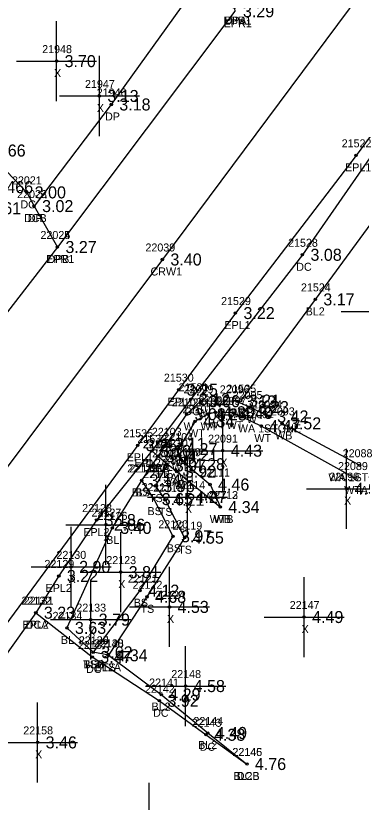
# Model space of a CAD drawing. Extents: x 2608745 to 2610333, y 641917 to 643463.
# Drawn here: x 2610015.6 to 2610058.8, y 641978.2 to 642076.5 of the extents above; entities that cross this region are included whole.
import ezdxf

# ---------------------------------------------------------------- set-up
doc = ezdxf.new("R2010")
doc.units = 0
for name, color, linetype in [('RD_DTM_BkLn1', 7, 'Continuous'), ('RD_DTM_BkLn2', 7, 'Continuous'), ('RD_DTM_BkLn_txCode', 7, 'Continuous'), ('RD_EX_BldgApp', 7, 'Continuous'), ('RD_EX_Conc', 7, 'Continuous'), ('RD_EX_Conc_txCode', 7, 'Continuous'), ('RD_EX_Driveway', 7, 'Continuous'), ('RD_EX_Driveway_txCode', 7, 'Continuous'), ('RD_EX_Misc', 7, 'Continuous'), ('RD_EX_Misc_txCode', 7, 'Continuous'), ('RD_EX_Road', 7, 'Continuous'), ('RD_EX_Road_txCode', 7, 'Continuous'), ('RD_EX_TX_Conc_ELEV', 7, 'Continuous'), ('RD_EX_TX_Driveway_ELEV', 7, 'Continuous'), ('RD_EX_TX_H2O_ELEV', 7, 'Continuous'), ('RD_EX_TX_Misc_ELEV', 7, 'Continuous'), ('RD_EX_TX_Road_ELEV', 7, 'Continuous'), ('RD_HC_Survey_ELEV', 7, 'Continuous'), ('RD_HC_Survey_txCode', 7, 'Continuous'), ('RD_SMD_Locator', 7, 'Continuous')]:
    doc.layers.add(name, color=color, linetype=linetype)

msp = doc.modelspace()

# ---------------------------------------------------------------- linework, layer by layer
at = {"layer": 'RD_DTM_BkLn1'}
for points in [[(2610092.08, 642124.262), (2610033.919, 642046.064), (2609975.15, 641967.52)], [(2610064.15, 642056.3), (2610053.021, 642041.077), (2610043.709, 642028.432)], [(2610031.326, 642018.462), (2610027.654, 642012.527), (2610021.996, 642000.031), (2610025.292, 641996.976)], [(2610027.171, 641996.605), (2610033.776, 641991.7), (2610039.588, 641986.9), (2610044.472, 641983.021)]]:
    msp.add_lwpolyline(points, dxfattribs=at)
at = {"layer": 'RD_DTM_BkLn2'}
for points in [[(2610057.977, 642018.749), (2610046.263, 642025.239), (2610042.801, 642026.891), (2610040.549, 642026.974), (2610039.555, 642026.7), (2610037.999, 642025.855), (2610035.879, 642022.371), (2610035.951, 642021.616), (2610036.833, 642020.479), (2610039.873, 642017.947), (2610041.157, 642015.128)], [(2610033.33, 642021.486), (2610031.326, 642018.462), (2610032.839, 642016.124), (2610035.243, 642011.478), (2610031.121, 642004.683), (2610025.292, 641996.976)], [(2610034.468, 642020.324), (2610033.051, 642017.75), (2610034.265, 642016.032), (2610036.693, 642011.302), (2610031.987, 642003.912), (2610027.171, 641996.605), (2610025.292, 641996.976)]]:
    msp.add_lwpolyline(points, dxfattribs=at)
at = {"layer": 'RD_EX_BldgApp'}
msp.add_line((2610058.557, 642020.354), (2610048.849, 642025.584), dxfattribs=at)
msp.add_lwpolyline([(2610047.256, 642026.455), (2610044.819, 642027.615), (2610043.225, 642028.33), (2610038.689, 642028.357), (2610036.938, 642026.725), (2610034.437, 642023.032), (2610033.33, 642021.486), (2610035.723, 642019.563), (2610041.157, 642015.128)], dxfattribs=at)
at = {"layer": 'RD_EX_Conc'}
for points in [[(2609961.016, 642063.114), (2609970.253, 642056.24), (2609973.77, 642053.725), (2609978.671, 642051.077), (2609980.569, 642050.362), (2609982.905, 642049.619), (2609986.846, 642049.978), (2609990.334, 642051.359), (2609992.677, 642052.953), (2609997.86, 642057.875), (2610001.755, 642060.528), (2610004.736, 642061.459), (2610008.347, 642061.293), (2610011.93, 642059.679), (2610016.967, 642054.45), (2610017.895, 642052.738)], [(2610062.865, 642060.944), (2610060.494, 642059.714), (2610051.415, 642046.652), (2610037.455, 642028.596), (2610032.589, 642022.148), (2610033.33, 642021.486)], [(2610018.112, 642001.928), (2610025.163, 641996.394), (2610033.543, 641990.921), (2610039.369, 641986.672), (2610044.472, 641983.021)]]:
    msp.add_lwpolyline(points, dxfattribs=at)
at = {"layer": 'RD_EX_Driveway'}
msp.add_lwpolyline([(2610042.94, 642077.419), (2610037.979, 642080.001), (2610027.537, 642065.432), (2610017.895, 642052.738), (2610020.807, 642047.622)], dxfattribs=at)
at = {"layer": 'RD_EX_Misc'}
for p, q in [((2610020.7, 642065.849), (2610020.7, 642075.849)), ((2610026.048, 642061.494), (2610026.048, 642071.494)), ((2610015.7, 642070.849), (2610025.7, 642070.849)), ((2610021.048, 642066.494), (2610031.048, 642066.494)), ((2610056.254, 642039.575), (2610066.254, 642039.575)), ((2610041.464, 642017.173), (2610041.464, 642027.173)), ((2610056.926, 642012.424), (2610056.926, 642022.424)), ((2610036.464, 642022.173), (2610046.464, 642022.173)), ((2610037.056, 642011.371), (2610037.056, 642021.371)), ((2610026.863, 642007.924), (2610026.863, 642017.924)), ((2610051.926, 642017.424), (2610061.926, 642017.424)), ((2610032.056, 642016.371), (2610042.056, 642016.371)), ((2610021.863, 642012.924), (2610031.863, 642012.924)), ((2610022.518, 642002.654), (2610022.518, 642012.654)), ((2610028.71, 642001.996), (2610028.71, 642011.996)), ((2610017.518, 642007.654), (2610027.518, 642007.654)), ((2610034.807, 641997.653), (2610034.807, 642007.653)), ((2610023.71, 642006.996), (2610033.71, 642006.996)), ((2610024.963, 641996.062), (2610024.963, 642006.062)), ((2610051.621, 641996.388), (2610051.621, 642006.388)), ((2610029.807, 642002.653), (2610039.807, 642002.653)), ((2610019.963, 642001.062), (2610029.963, 642001.062)), ((2610046.621, 642001.388), (2610056.621, 642001.388)), ((2610036.823, 641987.76), (2610036.823, 641997.76)), ((2610031.823, 641992.76), (2610041.823, 641992.76)), ((2610018.336, 641980.722), (2610018.336, 641990.722)), ((2610013.336, 641985.722), (2610023.336, 641985.722)), ((2610032.283, 641970.687), (2610032.283, 641980.687))]:
    msp.add_line(p, q, dxfattribs=at)
at = {"layer": 'RD_EX_Road'}
for points in [[(2610073.957, 642143.053), (2610073.967, 642133.893), (2610072.62, 642129.267), (2610072.125, 642123.733), (2610071.192, 642117.593), (2610042.94, 642077.419), (2610042.982, 642077.082), (2610020.807, 642047.622), (2610010.682, 642034.572), (2609995.36, 642013.506), (2609993.975, 642012.164), (2609992.649, 642010.593), (2609982.727, 641996.329), (2609971.725, 641982.02), (2609971.56, 641981.898), (2609965.999, 641974.618)], [(2610116.512, 642103.007), (2610109.419, 642106.335), (2610102.937, 642107.104), (2610095.974, 642105.732), (2610091.028, 642103.088), (2610067.446, 642071.713), (2610058.11, 642059.075), (2610043.044, 642039.371), (2610035.942, 642029.795), (2610030.832, 642022.851), (2609999.348, 641980.077), (2609984.87, 641960.622)], [(2610032.589, 642022.148), (2610025.693, 642013.504), (2610020.985, 642006.523), (2610018.112, 642001.928), (2610002.773, 641980.423), (2610001.184, 641979.118), (2609987.485, 641958.197)]]:
    msp.add_lwpolyline(points, dxfattribs=at)
at = {"layer": 'RD_SMD_Locator'}
for centre in [(2610020.7, 642070.849), (2610026.048, 642066.494), (2610027.537, 642065.432), (2610058.11, 642059.075), (2610016.967, 642054.45), (2610017.895, 642052.738), (2610017.895, 642052.738), (2610020.807, 642047.622), (2610020.807, 642047.622), (2610051.415, 642046.652), (2610033.919, 642046.064), (2610053.021, 642041.077), (2610043.044, 642039.371), (2610035.942, 642029.795), (2610037.455, 642028.596), (2610038.689, 642028.357), (2610043.225, 642028.33), (2610043.709, 642028.432), (2610040.549, 642026.974), (2610044.819, 642027.615), (2610036.938, 642026.725), (2610039.555, 642026.7), (2610042.801, 642026.891), (2610047.256, 642026.455), (2610037.999, 642025.855), (2610046.263, 642025.239), (2610048.849, 642025.584), (2610034.437, 642023.032), (2610030.832, 642022.851), (2610032.589, 642022.148), (2610032.589, 642022.148), (2610035.879, 642022.371), (2610041.464, 642022.173), (2610033.33, 642021.486), (2610033.33, 642021.486), (2610033.33, 642021.486), (2610035.951, 642021.616), (2610034.468, 642020.324), (2610036.833, 642020.479), (2610058.557, 642020.354), (2610035.723, 642019.563), (2610031.326, 642018.462), (2610031.326, 642018.462), (2610057.977, 642018.749), (2610033.051, 642017.75), (2610039.873, 642017.947), (2610056.926, 642017.424), (2610037.056, 642016.371), (2610032.839, 642016.124), (2610034.265, 642016.032), (2610041.157, 642015.128), (2610041.157, 642015.128), (2610025.693, 642013.504), (2610026.863, 642012.924), (2610027.654, 642012.527), (2610035.243, 642011.478), (2610036.693, 642011.302), (2610022.518, 642007.654), (2610020.985, 642006.523), (2610028.71, 642006.996), (2610031.121, 642004.683), (2610031.987, 642003.912), (2610034.807, 642002.653), (2610018.112, 642001.928), (2610018.112, 642001.928), (2610024.963, 642001.062), (2610051.621, 642001.388), (2610021.996, 642000.031), (2610025.292, 641996.976), (2610025.292, 641996.976), (2610025.292, 641996.976), (2610027.171, 641996.605), (2610027.171, 641996.605), (2610025.163, 641996.394), (2610036.823, 641992.76), (2610033.776, 641991.7), (2610033.543, 641990.921), (2610039.369, 641986.672), (2610039.588, 641986.9), (2610018.336, 641985.722), (2610044.472, 641983.021), (2610044.472, 641983.021)]:
    msp.add_circle(centre, 0.15, dxfattribs=at)

# ---------------------------------------------------------------- texts
at = {"layer": 'RD_DTM_BkLn_txCode'}
for s, p in [('21524', (2610051.226, 642042.077)), ('BL2', (2610051.816, 642039.077)), ('21525', (2610041.914, 642029.432)), ('BL2B', (2610042.032, 642026.432)), ('22106', (2610031.472, 642022.486)), ('22108', (2610032.633, 642021.324)), ('22125', (2610029.531, 642019.462)), ('22116', (2610029.791, 642019.462)), ('BSA', (2610032.063, 642019.486)), ('22115', (2610031.539, 642018.75)), ('TSA', (2610033.184, 642018.324)), ('BLA', (2610030.082, 642016.462)), ('BS', (2610030.547, 642016.462)), ('22117', (2610031.327, 642017.124)), ('22118', (2610032.753, 642017.032)), ('TS', (2610032.256, 642015.75)), ('22126', (2610025.835, 642013.527)), ('BS', (2610032.059, 642014.124)), ('TS', (2610033.47, 642014.032)), ('22120', (2610033.408, 642012.478)), ('22119', (2610035.181, 642012.302)), ('BL', (2610026.898, 642010.527)), ('BS', (2610034.463, 642009.478)), ('TS', (2610035.897, 642009.302)), ('22121', (2610029.609, 642005.683)), ('22122', (2610030.192, 642004.912)), ('BS', (2610030.341, 642002.683)), ('TS', (2610031.192, 642001.912)), ('22134', (2610020.201, 642001.031)), ('BL', (2610021.24, 641998.031)), ('22136', (2610023.473, 641997.976)), ('22135', (2610023.497, 641997.976)), ('22139', (2610023.497, 641997.976)), ('22140', (2610025.337, 641997.605)), ('22138', (2610025.376, 641997.605)), ('TSB', (2610024.025, 641994.976)), ('BSB', (2610024.04, 641994.976)), ('BLB', (2610024.064, 641994.976)), ('BL2A', (2610025.478, 641994.605)), ('TS', (2610026.376, 641994.605)), ('22141', (2610032.264, 641992.7)), ('BL2', (2610032.571, 641989.7)), ('22144', (2610037.793, 641987.9)), ('BL2', (2610038.383, 641984.9)), ('22146', (2610042.654, 641984.021)), ('BL2B', (2610042.795, 641981.021))]:
    msp.add_text(s, height=1, dxfattribs=at).set_placement(p)
at = {"layer": 'RD_EX_Conc_txCode'}
for s, p in [('22021', (2610015.132, 642055.45)), ('22022', (2610015.776, 642053.738)), ('DC', (2610016.187, 642052.45)), ('DCB', (2610016.643, 642050.738)), ('21528', (2610049.62, 642047.652)), ('DC', (2610050.635, 642044.652)), ('21531', (2610035.943, 642029.596)), ('DC', (2610036.675, 642026.596)), ('21532', (2610030.794, 642023.148)), ('21534', (2610031.535, 642022.486)), ('DC', (2610031.809, 642020.148)), ('DCB', (2610032.078, 642019.486)), ('22132', (2610016.317, 642002.928)), ('DCA', (2610016.844, 641999.928)), ('22137', (2610023.368, 641997.394)), ('DC', (2610024.384, 641994.394)), ('22142', (2610031.747, 641991.921)), ('DC', (2610032.763, 641988.921)), ('22143', (2610037.574, 641987.672)), ('DC', (2610038.59, 641984.672)), ('22145', (2610042.677, 641984.021)), ('DCB', (2610043.22, 641981.021))]:
    msp.add_text(s, height=1, dxfattribs=at).set_placement(p)
at = {"layer": 'RD_EX_Driveway_txCode'}
for s, p in [('DPA', (2610041.673, 642075.419)), ('21946', (2610025.718, 642066.432)), ('DP', (2610026.757, 642063.432)), ('22023', (2610015.776, 642053.738)), ('DP', (2610017.115, 642050.738)), ('22024', (2610018.688, 642048.622)), ('DPB', (2610019.555, 642045.622))]:
    msp.add_text(s, height=1, dxfattribs=at).set_placement(p)
at = {"layer": 'RD_EX_Misc_txCode'}
for s, p in [('21948', (2610018.905, 642071.849)), ('X', (2610020.385, 642068.849)), ('21947', (2610024.253, 642067.494)), ('X', (2610025.733, 642064.494)), ('22099', (2610036.571, 642029.357)), ('22096', (2610041.083, 642029.33)), ('22095', (2610042.701, 642028.615)), ('22102', (2610035.103, 642027.725)), ('22100', (2610037.681, 642027.7)), ('22098', (2610038.431, 642027.974)), ('22097', (2610040.683, 642027.891)), ('22094', (2610045.138, 642027.455)), ('22101', (2610036.447, 642026.855)), ('W', (2610038.319, 642026.357)), ('W', (2610042.855, 642026.33)), ('22092', (2610044.145, 642026.239)), ('22093', (2610046.731, 642026.584)), ('W', (2610044.449, 642025.615)), ('W', (2610036.568, 642024.725)), ('WT', (2610038.697, 642024.7)), ('WT', (2610039.691, 642024.974)), ('WT', (2610041.943, 642024.891)), ('WA 1STONE', (2610043.355, 642024.455)), ('22103', (2610032.603, 642024.032)), ('22104', (2610034.044, 642023.371)), ('WT', (2610037.14, 642023.855)), ('22091', (2610039.629, 642023.173)), ('WT', (2610045.405, 642023.239)), ('WB', (2610048.007, 642023.584)), ('22105', (2610031.496, 642022.486)), ('22107', (2610034.117, 642022.616)), ('22109', (2610034.998, 642021.479)), ('22088', (2610056.439, 642021.354)), ('W', (2610034.067, 642021.032)), ('22110', (2610034.171, 642020.563)), ('WT', (2610035.02, 642020.371)), ('W', (2610032.96, 642019.486)), ('WT', (2610035.093, 642019.616)), ('X', (2610041.149, 642020.173)), ('22089', (2610055.859, 642019.749)), ('WT', (2610035.974, 642018.479)), ('22111', (2610038.644, 642018.947)), ('WA 1STONE', (2610054.655, 642018.354)), ('22090', (2610054.769, 642018.424)), ('W', (2610035.353, 642017.563)), ('22114', (2610035.544, 642017.371)), ('WTA', (2610056.631, 642016.749)), ('WT', (2610039.015, 642015.947)), ('22112', (2610039.645, 642016.128)), ('22113', (2610039.645, 642016.128)), ('X', (2610056.611, 642015.424)), ('X', (2610036.741, 642014.371)), ('22127', (2610025.067, 642013.924)), ('WTB', (2610039.826, 642013.128)), ('WB', (2610040.314, 642013.128)), ('X', (2610026.548, 642010.924)), ('22130', (2610020.684, 642008.654)), ('22123', (2610026.915, 642007.996)), ('X', (2610022.203, 642005.654)), ('X', (2610028.395, 642004.996)), ('22124', (2610033.012, 642003.653)), ('22133', (2610023.168, 642002.062)), ('22147', (2610049.826, 642002.388)), ('X', (2610034.492, 642000.653)), ('X', (2610024.648, 641999.062)), ('X', (2610051.306, 641999.388)), ('22148', (2610035.028, 641993.76)), ('X', (2610036.508, 641990.76)), ('22158', (2610016.541, 641986.722)), ('X', (2610018.021, 641983.722))]:
    msp.add_text(s, height=1, dxfattribs=at).set_placement(p)
at = {"layer": 'RD_EX_Road_txCode'}
for s, p in [('EPR1', (2610041.547, 642075.419)), ('EPR1', (2610041.589, 642075.082)), ('21522', (2610056.314, 642060.075)), ('EPL1', (2610056.74, 642057.075)), ('22025', (2610018.688, 642048.622)), ('EPR1', (2610019.413, 642045.622)), ('21529', (2610041.249, 642040.371)), ('EPL1', (2610041.674, 642037.371)), ('21530', (2610034.107, 642030.795)), ('EPL1', (2610034.572, 642027.795)), ('21535', (2610029.037, 642023.851)), ('21533', (2610030.794, 642023.148)), ('EPL1', (2610029.462, 642020.851)), ('EPL2A', (2610030.447, 642020.148)), ('22128', (2610023.898, 642014.504)), ('EPL2', (2610024.04, 642011.504)), ('22129', (2610019.19, 642007.523)), ('EPL2', (2610019.331, 642004.523)), ('22131', (2610016.6, 642002.928)), ('EPL2', (2610016.458, 641999.928))]:
    msp.add_text(s, height=1, dxfattribs=at).set_placement(p)
at = {"layer": 'RD_EX_TX_Conc_ELEV'}
for s, p in [('3.66', (2610012.93, 642058.929)), ('3.00', (2610017.967, 642053.7)), ('3.02', (2610018.895, 642051.988)), ('3.08', (2610052.415, 642045.902)), ('3.12', (2610038.455, 642027.846)), ('3.10', (2610033.589, 642021.398)), ('3.04', (2610034.33, 642020.736)), ('3.23', (2610019.112, 642001.178)), ('3.47', (2610026.163, 641995.644)), ('3.92', (2610034.543, 641990.171)), ('4.38', (2610040.369, 641985.922)), ('4.76', (2610045.472, 641982.271))]:
    msp.add_text(s, height=1.5, dxfattribs=at).set_placement(p)
at = {"layer": 'RD_EX_TX_Driveway_ELEV'}
for s, p in [('3.18', (2610028.537, 642064.682)), ('3.02', (2610018.895, 642051.988)), ('3.27', (2610021.807, 642046.872))]:
    msp.add_text(s, height=1.5, dxfattribs=at).set_placement(p)
at = {"layer": 'RD_EX_TX_H2O_ELEV'}
for s, p in [('EL=1.466', (2610009.129, 642054.352)), ('2.61', (2610012.37, 642051.721))]:
    msp.add_text(s, height=1.5, dxfattribs=at).set_placement(p)
at = {"layer": 'RD_EX_TX_Misc_ELEV'}
for s, p in [('3.70', (2610021.7, 642070.099)), ('3.13', (2610027.048, 642065.744)), ('3.17', (2610054.021, 642040.327)), ('3.06', (2610039.689, 642027.607)), ('3.12', (2610044.225, 642027.58)), ('3.21', (2610044.709, 642027.682)), ('3.23', (2610045.819, 642026.865)), ('3.08', (2610037.938, 642025.975)), ('4.25', (2610040.555, 642025.95)), ('4.30', (2610041.549, 642026.224)), ('4.40', (2610043.801, 642026.141)), ('3.42', (2610048.256, 642025.705)), ('4.34', (2610038.999, 642025.105)), ('3.52', (2610049.849, 642024.834)), ('4.47', (2610047.263, 642024.489)), ('3.11', (2610035.437, 642022.282)), ('3.04', (2610034.33, 642020.736)), ('3.04', (2610034.33, 642020.736)), ('4.27', (2610036.879, 642021.621)), ('4.21', (2610036.951, 642020.866)), ('4.43', (2610042.464, 642021.423)), ('4.28', (2610037.833, 642019.729)), ('3.97', (2610035.468, 642019.574)), ('3.92', (2610036.723, 642018.813)), ('3.14', (2610032.326, 642017.712)), ('3.14', (2610032.326, 642017.712)), ('3.96', (2610034.051, 642017)), ('4.46', (2610040.873, 642017.197)), ('4.51', (2610057.926, 642016.674)), ('3.65', (2610033.839, 642015.374)), ('4.21', (2610035.265, 642015.282)), ('4.27', (2610038.056, 642015.621)), ('4.34', (2610042.157, 642014.378)), ('4.34', (2610042.157, 642014.378)), ('2.86', (2610027.863, 642012.174)), ('3.40', (2610028.654, 642011.777)), ('3.97', (2610036.243, 642010.728)), ('4.55', (2610037.693, 642010.552)), ('2.90', (2610023.518, 642006.904)), ('3.81', (2610029.71, 642006.246)), ('4.12', (2610032.121, 642003.933)), ('4.68', (2610032.987, 642003.162)), ('4.53', (2610035.807, 642001.903)), ('3.79', (2610025.963, 642000.312)), ('4.49', (2610052.621, 642000.638)), ('3.63', (2610022.996, 641999.281)), ('3.62', (2610026.292, 641996.226)), ('3.62', (2610026.292, 641996.226)), ('3.62', (2610026.292, 641996.226)), ('4.34', (2610028.171, 641995.855)), ('4.34', (2610028.171, 641995.855)), ('4.58', (2610037.823, 641992.01)), ('4.29', (2610034.776, 641990.95)), ('4.49', (2610040.588, 641986.15)), ('3.46', (2610019.336, 641984.972)), ('4.76', (2610045.472, 641982.271))]:
    msp.add_text(s, height=1.5, dxfattribs=at).set_placement(p)
at = {"layer": 'RD_EX_TX_Road_ELEV'}
for s, p in [('3.29', (2610043.982, 642076.332)), ('3.27', (2610021.807, 642046.872)), ('3.22', (2610044.044, 642038.621)), ('3.25', (2610036.942, 642029.045)), ('3.26', (2610031.832, 642022.101)), ('3.10', (2610033.589, 642021.398)), ('3.18', (2610026.693, 642012.754)), ('3.22', (2610021.985, 642005.773)), ('3.23', (2610019.112, 642001.178))]:
    msp.add_text(s, height=1.5, dxfattribs=at).set_placement(p)
at = {"layer": 'RD_HC_Survey_ELEV'}
msp.add_text('3.40', height=1.5, dxfattribs=at).set_placement((2610034.919, 642045.314))
at = {"layer": 'RD_HC_Survey_txCode'}
for s, p in [('22039', (2610031.801, 642047.064)), ('CRW1', (2610032.438, 642044.064))]:
    msp.add_text(s, height=1, dxfattribs=at).set_placement(p)

doc.saveas('drawing.dxf')
